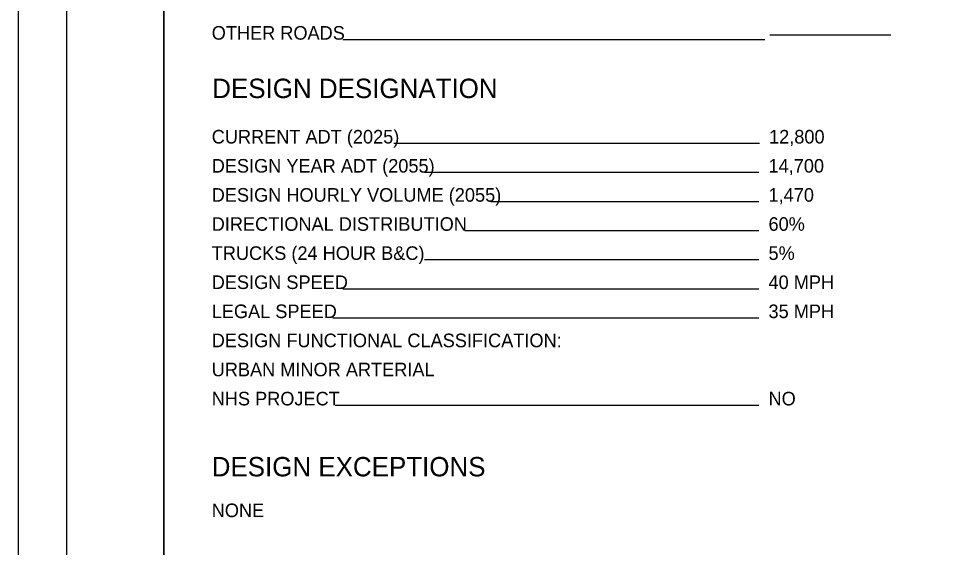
# Model space of a CAD drawing. Extents: x -5.4 to 71.3, y -12 to 22.
# Drawn here: x 0 to 9.45, y 5.64 to 11.1 of the extents above; entities that cross this region are included whole.
import ezdxf

# ---------------------------------------------------------------- set-up
doc = ezdxf.new("R2010")
doc.units = 0
for name, color, linetype in [('SH_Border', 7, 'Continuous'), ('SH_Cut_Line', 7, 'Continuous'), ('SH_Data', 7, 'Continuous'), ('SH_Text', 7, 'Continuous')]:
    doc.layers.add(name, color=color, linetype=linetype)

msp = doc.modelspace()

# ---------------------------------------------------------------- linework, layer by layer
at = {"layer": 'SH_Border'}
for points in [[(0.5, 21.5), (1.5, 21.5), (1.5, 0.5), (0.5, 0.5)], [(1.5, 21.5), (33.5, 21.5), (33.5, 0.5), (1.5, 0.5)]]:
    msp.add_lwpolyline(points, close=True, dxfattribs=at)
at = {"layer": 'SH_Cut_Line'}
msp.add_lwpolyline([(0, 0), (34, 0), (34, 22), (0, 22)], close=True, dxfattribs=at)
at = {"layer": 'SH_Data'}
for p, q in [((7.7, 10.8767), (3.3471, 10.8767)), ((9, 10.9223), (7.75, 10.9223)), ((7.6424, 9.8062), (3.871, 9.8062)), ((7.6368, 9.5062), (4.1885, 9.5062)), ((7.6368, 9.2062), (4.8723, 9.2062)), ((7.6368, 8.9062), (4.6037, 8.9062)), ((7.6368, 8.6062), (4.1885, 8.6062)), ((7.6368, 8.3062), (3.346, 8.3062)), ((7.6368, 8.0062), (3.2422, 8.0062)), ((7.6368, 7.1062), (3.2669, 7.1062))]:
    msp.add_line(p, q, dxfattribs=at)

# ---------------------------------------------------------------- texts
msp.add_text('DESIGN DESIGNATION', height=0.2, dxfattribs=at).set_placement((2, 10.2747))
at = {"layer": 'SH_Text'}
for s, height, p in [('OTHER ROADS', 0.14, (1.9944, 10.8767)), ('CURRENT ADT (2025)', 0.14, (1.9944, 9.8062)), ('12,800', 0.14, (7.7424, 9.8062)), ('DESIGN YEAR ADT (2055)', 0.14, (1.9944, 9.5062)), ('14,700', 0.14, (7.7368, 9.5062)), ('DESIGN HOURLY VOLUME (2055)', 0.14, (1.9944, 9.2062)), ('1,470', 0.14, (7.7368, 9.2062)), ('DIRECTIONAL DISTRIBUTION', 0.14, (1.9944, 8.9062)), ('60%', 0.14, (7.7368, 8.9062)), ('TRUCKS (24 HOUR B&C)', 0.14, (1.9944, 8.6062)), ('5%', 0.14, (7.7368, 8.6062)), ('DESIGN SPEED', 0.14, (1.9944, 8.3062)), ('40 MPH', 0.14, (7.7368, 8.3062)), ('LEGAL SPEED', 0.14, (1.9944, 8.0062)), ('35 MPH', 0.14, (7.7368, 8.0062)), ('DESIGN FUNCTIONAL CLASSIFICATION:', 0.14, (1.9944, 7.7062)), ('URBAN MINOR ARTERIAL', 0.14, (1.9944, 7.4062)), ('NHS PROJECT', 0.14, (1.9944, 7.1062)), ('NO', 0.14, (7.7368, 7.1062)), ('DESIGN EXCEPTIONS', 0.2, (1.9944, 6.3744)), ('NONE', 0.14, (1.9944, 5.9544))]:
    msp.add_text(s, height=height, dxfattribs=at).set_placement(p)

doc.saveas('drawing.dxf')
